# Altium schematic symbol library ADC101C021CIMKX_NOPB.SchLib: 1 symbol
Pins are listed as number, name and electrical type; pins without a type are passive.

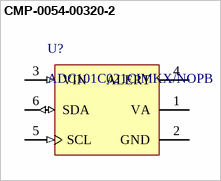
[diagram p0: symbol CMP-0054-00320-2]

## CMP-0054-00320-2
designator U?, comment ADC101C021CIMKX/NOPB
I2C-Compatible, 10-Bit Analog-to-Digital Converter (ADC) with Alert Pin, 6-pin Tiny SOT23, Pb-Free; Manufacturer: National Semiconductor; PackageTopMarking: X33C*XTT; PowerWise: N; CompType: ADC IC
footprint MK06A_L (SOT23, 6-Leads, Body 3.0x1.7mm, Pitch 0.95mm, Lead Span 2.9mm, IPC High Density)
footprint MK06A_N (SOT23, 6-Leads, Body 3.0x1.7mm, Pitch 0.95mm, Lead Span 2.9mm, IPC Medium Density)
footprint MK06A_M (SOT23, 6-Leads, Body 3.0x1.7mm, Pitch 0.95mm, Lead Span 2.9mm, IPC Low Density)
pins: 1 VA (power), 2 GND (power), 3 VIN (in), 4 ALERT (oc), 5 SCL (in), 6 SDA (io)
